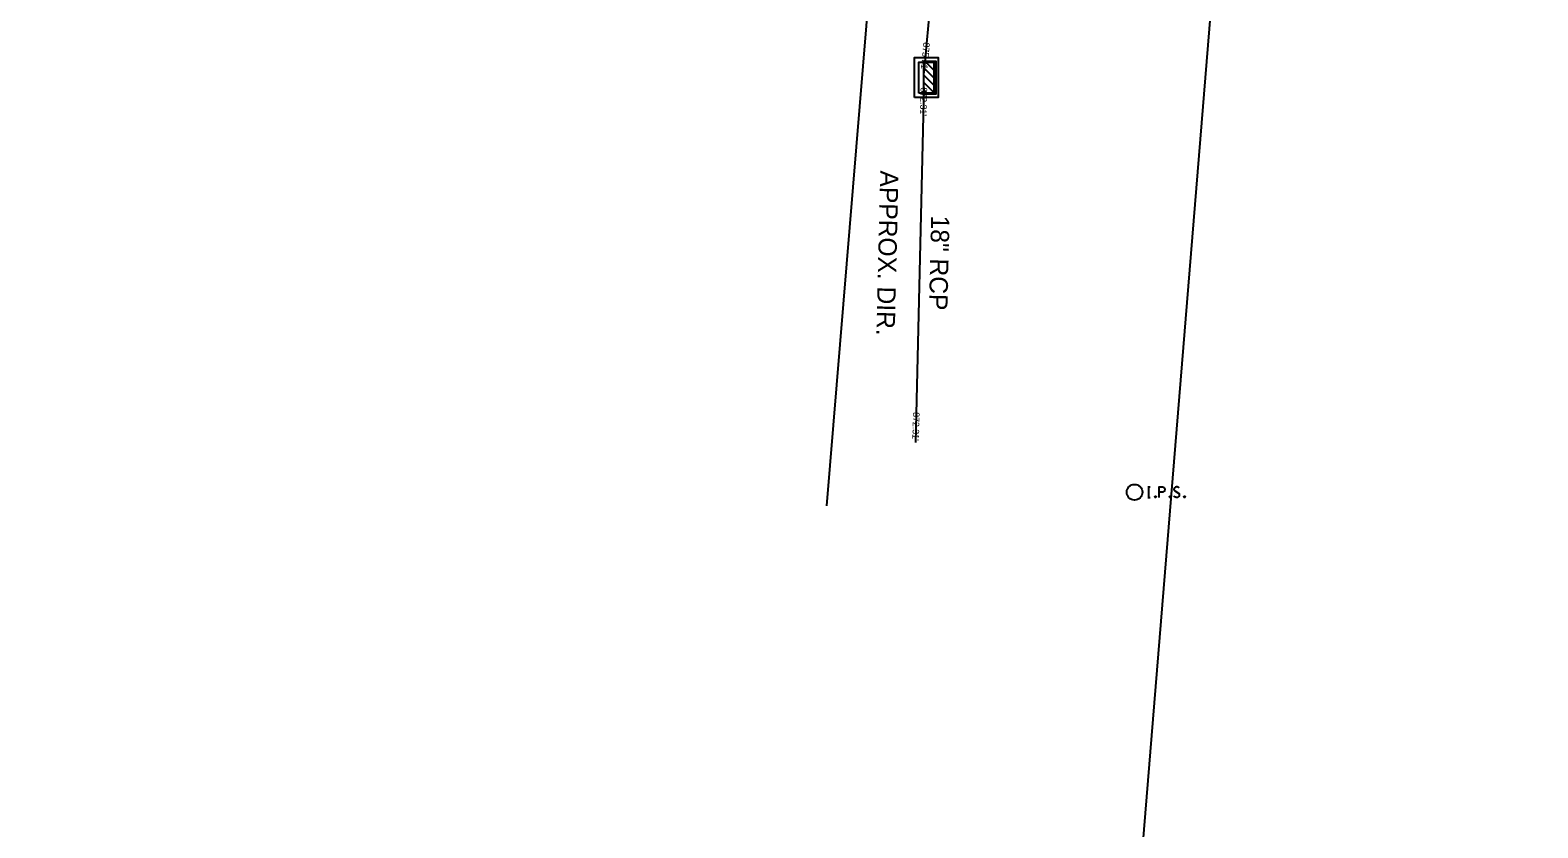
# Model space of a CAD drawing. Extents: x 1380440 to 1381945, y 468756 to 470369.
# Drawn here: x 1381364.5 to 1381594.3, y 468877.3 to 468998.9 of the extents above; entities that cross this region are included whole.
import ezdxf

# ---------------------------------------------------------------- set-up
doc = ezdxf.new("R2010")
doc.units = 0
for name, color, linetype in [('PV_P_Curb_Ramp', 7, 'Continuous'), ('PV_P_Joint', 7, 'Continuous'), ('PV_P_Walk', 7, 'Continuous'), ('RW_X_CL', 7, 'Continuous'), ('SC_Scratch1', 7, 'Continuous'), ('UT_X_Gas', 7, 'Continuous'), ('UT_X_Sanitary_Line', 7, 'Continuous'), ('X-CL', 7, 'Continuous')]:
    doc.layers.add(name, color=color, linetype=linetype)

msp = doc.modelspace()

# ---------------------------------------------------------------- linework, layer by layer
at = {"layer": 'PV_P_Curb_Ramp'}
for p, q in [((1381501.08, 468994.04), (1381501.08, 468994.04)), ((1381499.29, 468991.66), (1381499.29, 468991.66)), ((1381499.96, 468991.66), (1381499.96, 468991.66)), ((1381500.71, 468991.66), (1381500.71, 468991.66)), ((1381500.71, 468991.66), (1381500.71, 468991.66)), ((1381501.08, 468991.66), (1381501.08, 468991.66)), ((1381502.21, 468991.66), (1381502.21, 468991.66)), ((1381502.87, 468991.66), (1381502.87, 468991.66)), ((1381501.08, 468989.29), (1381501.08, 468989.29))]:
    msp.add_line(p, q, dxfattribs=at)
at = {"layer": 'PV_P_Joint'}
for p, q in [((1381502.54, 468992.48), (1381500.85, 468994.16)), ((1381502.54, 468993.61), (1381501.98, 468994.16)), ((1381502.54, 468991.35), (1381500.71, 468993.18)), ((1381502.54, 468990.22), (1381500.71, 468992.05)), ((1381502.47, 468989.16), (1381500.71, 468990.92)), ((1381501.33, 468989.16), (1381500.71, 468989.79))]:
    msp.add_line(p, q, dxfattribs=at)
for points in [[(1381499.29, 468988.62), (1381499.29, 468994.71), (1381502.87, 468994.71), (1381502.87, 468988.62)], [(1381499.96, 468989.29), (1381499.96, 468994.04), (1381502.21, 468994.04), (1381502.21, 468989.29)], [(1381500.71, 468989.16), (1381500.71, 468994.16), (1381502.54, 468994.16), (1381502.54, 468989.16)]]:
    msp.add_lwpolyline(points, close=True, dxfattribs=at)
at = {"layer": 'PV_P_Walk'}
for points in [[(1381534.83, 468929.27), (1381535.18, 468929.27)], [(1381535, 468927.67), (1381535, 468929.27)], [(1381536.57, 468927.67), (1381536.57, 468929.27), (1381537.1, 468929.27), (1381537.15, 468929.26), (1381537.23, 468929.24), (1381537.26, 468929.21), (1381537.3, 468929.19), (1381537.34, 468929.12), (1381537.37, 468929.06), (1381537.4, 468928.96), (1381537.4, 468928.81), (1381537.39, 468928.76), (1381537.36, 468928.68), (1381537.32, 468928.59), (1381537.28, 468928.56), (1381537.24, 468928.53), (1381537.19, 468928.5), (1381537.1, 468928.49), (1381536.57, 468928.49)], [(1381539.58, 468929.16), (1381539.56, 468929.19), (1381539.52, 468929.21), (1381539.42, 468929.25), (1381539.3, 468929.27), (1381539.22, 468929.27), (1381539.18, 468929.27), (1381539.04, 468929.24), (1381538.92, 468929.16), (1381538.84, 468929.06), (1381538.82, 468928.96), (1381538.82, 468928.88), (1381538.84, 468928.78), (1381538.93, 468928.69), (1381539.53, 468928.32), (1381539.59, 468928.27), (1381539.61, 468928.22), (1381539.63, 468928.14), (1381539.63, 468928.06), (1381539.62, 468927.99), (1381539.61, 468927.94), (1381539.59, 468927.87), (1381539.57, 468927.82), (1381539.55, 468927.79), (1381539.51, 468927.75), (1381539.48, 468927.72), (1381539.44, 468927.7), (1381539.4, 468927.69), (1381539.3, 468927.67), (1381539.15, 468927.67), (1381539.05, 468927.7), (1381538.91, 468927.79), (1381538.82, 468927.86)], [(1381534.83, 468927.67), (1381535.18, 468927.67)], [(1381535.96, 468927.89), (1381536.02, 468927.89), (1381536.05, 468927.86), (1381536.08, 468927.81), (1381536.08, 468927.75), (1381536.05, 468927.7), (1381536.02, 468927.67), (1381535.96, 468927.67), (1381535.93, 468927.7), (1381535.9, 468927.75), (1381535.9, 468927.81), (1381535.93, 468927.86), (1381535.96, 468927.89)], [(1381538.21, 468927.89), (1381538.27, 468927.89), (1381538.3, 468927.86), (1381538.33, 468927.81), (1381538.33, 468927.75), (1381538.3, 468927.7), (1381538.27, 468927.67), (1381538.21, 468927.67), (1381538.18, 468927.7), (1381538.15, 468927.75), (1381538.15, 468927.81), (1381538.18, 468927.86), (1381538.21, 468927.89)], [(1381540.39, 468927.89), (1381540.45, 468927.89), (1381540.48, 468927.86), (1381540.52, 468927.81), (1381540.52, 468927.75), (1381540.48, 468927.7), (1381540.45, 468927.67), (1381540.39, 468927.67), (1381540.36, 468927.7), (1381540.33, 468927.75), (1381540.33, 468927.81), (1381540.36, 468927.86), (1381540.39, 468927.89)]]:
    msp.add_lwpolyline(points, dxfattribs=at)
msp.add_circle((1381532.81, 468928.47), 1.2, dxfattribs=at)
at = {"layer": 'UT_X_Gas'}
msp.add_lwpolyline([(1381485.9, 468926.41), (1381594.27, 470237.89), (1380558, 470279.29)], dxfattribs=at)
at = {"layer": 'UT_X_Sanitary_Line'}
msp.add_line((1381524.42, 468755.72), (1381547.56, 469040.34), dxfattribs=at)
at = {"layer": 'X-CL'}
for p, q in [((1381528.04, 469296.45), (1381500.71, 468992.41)), ((1381500.71, 468990.16), (1381499.44, 468936.03))]:
    msp.add_line(p, q, dxfattribs=at)

# ---------------------------------------------------------------- texts
at = {"layer": 'RW_X_CL'}
for s, p in [('APPROX. DIR.', (1381494.05, 468977.53)), ('18" RCP', (1381501.82, 468970.66))]:
    msp.add_text(s, height=2.8, rotation=268.6571, dxfattribs=at).set_placement(p)
at = {"layer": 'SC_Scratch1'}
for s, rotation, p in [("875.31'", 264.8634, (1381500.62, 468997.07)), ("872.31'", 268.6571, (1381500.21, 468990.18)), ("872.31'", 268.6571, (1381499.05, 468940.68))]:
    msp.add_text(s, height=1, rotation=rotation, dxfattribs=at).set_placement(p)

doc.saveas('drawing.dxf')
